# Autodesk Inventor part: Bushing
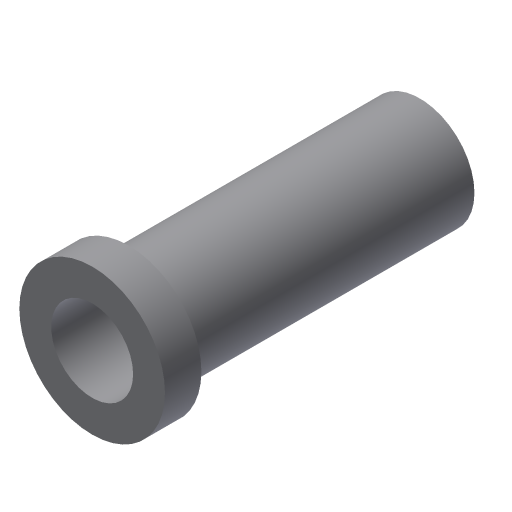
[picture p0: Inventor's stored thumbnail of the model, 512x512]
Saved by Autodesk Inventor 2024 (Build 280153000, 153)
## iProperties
Shininess: 77.0
Length Units: 11269
Angle Units: 11279
Time Units: 11290
Mass Units: 11283
Length Display Precision: 3
Angle Display Precision: 2
Created: 2002-02
Part Number: Bushing
Document SubType Name: Modeling
Designer: ***
Density: 1 g/cm^3
Material: Generic
Appearance: Default
Density: 0.0
Volumn: 0.0
Area: 0.0
PropertySet Name: Model Information
Control State: 0
Master: False
Checked Out: False
Author: ***
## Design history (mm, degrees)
sketch "Sketch1"
  geometry: L1 (6.25, 50.44)-(6.25, 5.44); L2 (6.25, 5.44)-(10.625, 5.44); L3 (10.625, 5.44)-(10.625, 10.44); L4 (10.625, 10.44)-(8.125, 10.44); L5 (8.125, 10.44)-(8.125, 50.44); L6 (8.125, 50.44)-(6.25, 50.44); L7 (0.625, 34.884)-(0.625, 0)
  constraints: 14 end point, 4 parallel, 2 perpendicular, 1 vertical
  dimensions: "d0" = 20 diameter of L3 L7; "d1" = 11.25 diameter of L1 L7; "d2" = 15 diameter of L5 L7; "d4" = 5 distance of L2.end L3.end; "d5" = 45 distance of L1.start L1.end
revolve "Revolution1" sketch "Sketch1" stored, may be unused: angle "d3" = 90 deg
body "Solid1"
